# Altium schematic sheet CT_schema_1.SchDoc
size 392 x 258 mm
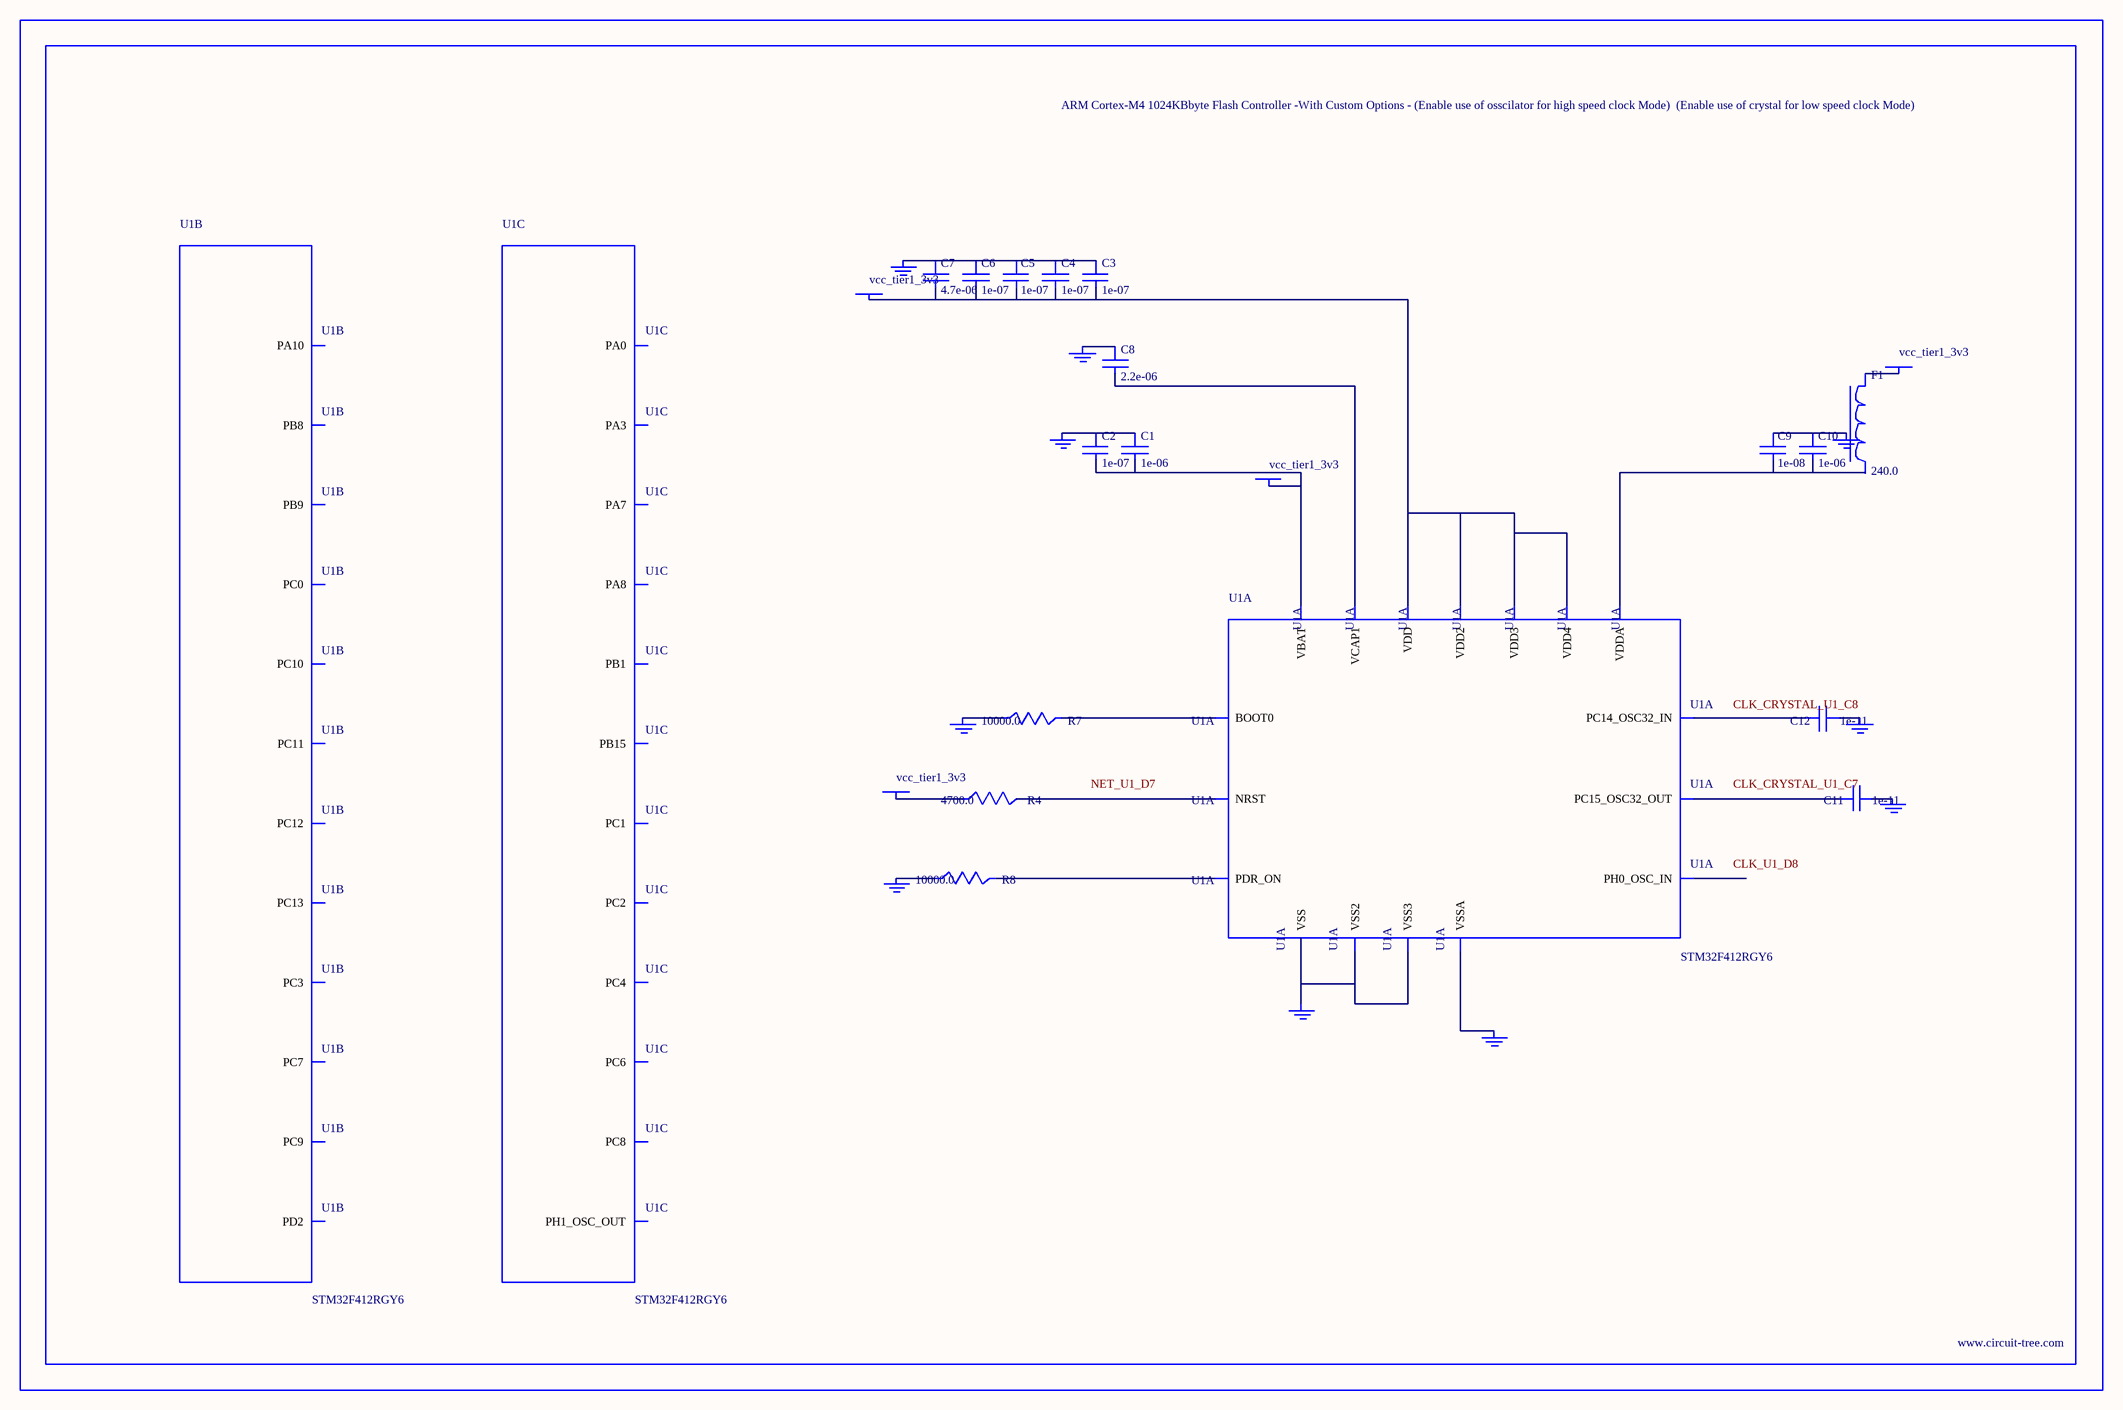
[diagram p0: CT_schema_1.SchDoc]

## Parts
BORDER0  (no value)
C1  1e-06  [C0603]
C2  1e-07  [C0603]
C3  1e-07  [C0603]
C4  1e-07  [C0603]
C5  1e-07  [C0603]
C6  1e-07  [C0603]
C7  4.7e-06  [C0603]
C8  2.2e-06  [C0603]
C9  1e-08  [C0603]
C10  1e-06  [C0603]
C11  1e-11  [C0402]
C12  1e-11  [C0402]
F1  240.0  [L0603]
GND_INSTANCE_0_0  (no value)
GND_INSTANCE_0_1  (no value)
GND_INSTANCE_0_2  (no value)
GND_INSTANCE_0_3  (no value)
GND_INSTANCE_0_4  (no value)
GND_INSTANCE_0_5  (no value)
GND_INSTANCE_0_6  (no value)
GND_INSTANCE_0_7  (no value)
GND_INSTANCE_0_8  (no value)
GND_INSTANCE_0_9  (no value)
POWER_INSTANCE_0_0  vcc_tier1_3v3
POWER_INSTANCE_0_1  vcc_tier1_3v3
POWER_INSTANCE_0_2  vcc_tier1_3v3
POWER_INSTANCE_0_3  vcc_tier1_3v3
R4  4700.0  [R0603]
R7  10000.0  [R0603]
R8  10000.0  [R0603]
U1  STM32F412RGY6  [WLCSP64]  (parts A,B,C of 7)

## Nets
NetC1_1: C1.1 C2.1 GND_INSTANCE_0_0.0(GND)
NetC1_2: C1.2 C2.2 POWER_INSTANCE_0_0.0(PWR) U1.B7(VBAT)
NetC3_1: C3.1 C4.1 C5.1 C6.1 C7.1 GND_INSTANCE_0_2.0(GND)
NetC3_2: C3.2 C4.2 C5.2 C6.2 C7.2 POWER_INSTANCE_0_2.0(PWR) U1.A1(VDD) U1.A8(VDD2) U1.H1(VDD3) U1.H7(VDD4)
NetC8_1: C8.1 GND_INSTANCE_0_4.0(GND)
NetC8_2: C8.2 U1.H3(VCAP1)
NetC9_1: C9.1 C10.1 GND_INSTANCE_0_1.0(GND)
NetC9_2: C9.2 C10.2 U1.F7(VDDA)
NetC11_1: C11.1 GND_INSTANCE_0_6.0(GND)
NetC11_2: C11.2 U1.C7(PC15_OSC32_OUT)
NetC12_1: C12.1 GND_INSTANCE_0_7.0(GND)
NetC12_2: C12.2 U1.C8(PC14_OSC32_IN)
NetF1_1: F1.1 POWER_INSTANCE_0_1.0(PWR)
NetGND_INSTANCE_0_3_0: GND_INSTANCE_0_3.0(GND) R7.1
NetGND_INSTANCE_0_5_0: GND_INSTANCE_0_5.0(GND) R8.1
NetGND_INSTANCE_0_8_0: GND_INSTANCE_0_8.0(GND) U1.G8(VSSA)
NetGND_INSTANCE_0_9_0: GND_INSTANCE_0_9.0(GND) U1.A7(VSS) U1.B1(VSS2) U1.H2(VSS3)
NetPOWER_INSTANCE_0_3_0: POWER_INSTANCE_0_3.0(PWR) R4.1
NetR4_2: R4.2 U1.D7(NRST)
NetR7_2: R7.2 U1.D4(BOOT0)
NetR8_2: R8.2 U1.C6(PDR_ON)

Not connected (* = marked no-connect by the designer): F1 2; U1 A3(PC12) A4(PD2) B3(PC11) B6(PB9) B8(PC13) C3(PC10) C5(PB8) D2(PA10) D5(PC0) D6(PC3) D8(PH0_OSC_IN) E1(PC7) E2(PC9) E3(PA8) E4(PC4) E5(PA7) E6(PA0) E7(PC2) E8(PH1_OSC_OUT) F1(PC6) F2(PB15) F3(PC8) F4(PB1) F6(PA3) F8(PC1)

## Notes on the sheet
- Labels drawn without touching a wire or pin: CLK_CRYSTAL_U1_C7, CLK_CRYSTAL_U1_C8, CLK_U1_D8, NET_U1_D7

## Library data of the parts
BORDER0 = BORDER_PAGE0
C1 C10 = C0603C105K3RACTU
C2-C6 = 06035C104K4Z2A
C7 = GRM188R6YA475KE15D
C8 = C0603C225K8RACTU
C9 = 06035C103K4Z2A
C11 C12 = C0402C100K3GACTU
F1 = Z0603C241ASMST
GND_INSTANCE_0_0-GND_INSTANCE_0_9 = GND
POWER_INSTANCE_0_0-POWER_INSTANCE_0_3 = PWR
R4 = RC0603JR-074K7L
R7 R8 = RC0603JR-0710KL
